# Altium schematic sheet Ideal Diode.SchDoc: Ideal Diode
size A4; Date: Not shown in title block; ApprovedBy: Hely Zhang; CheckedBy: Not shown in title block; Author: Not shown in title block; CompanyName: Not shown in title block; DrawnBy: Hely Zhang; Engineer: Not shown in title block; Organization: Not shown in title block; Address1: Not shown in title block; Address2: Not shown in title block; Address3: Not shown in title block; Address4: Not shown in title block; DocumentNumber: 1; Revision: Use project parameter SCH_Rev; SheetNumber: 15; SheetTotal: 15; PageSetup: Record=PageOptions¦CenterHorizontal=True¦CenterVertical=True¦PrintScale=0.93¦XCorrection=1.00¦YCorrection=1.00¦PrintKind=0¦BorderSize=5000000¦LeftOffset=0¦BottomOffset=0¦Orientation=2¦PaperLength=1000¦PaperWidth=1000¦Scale=100¦PaperSource=15¦PrintQuality=600¦MediaType=1¦DitherType=10¦PaperKind=Letter¦PrintScaleMode=1
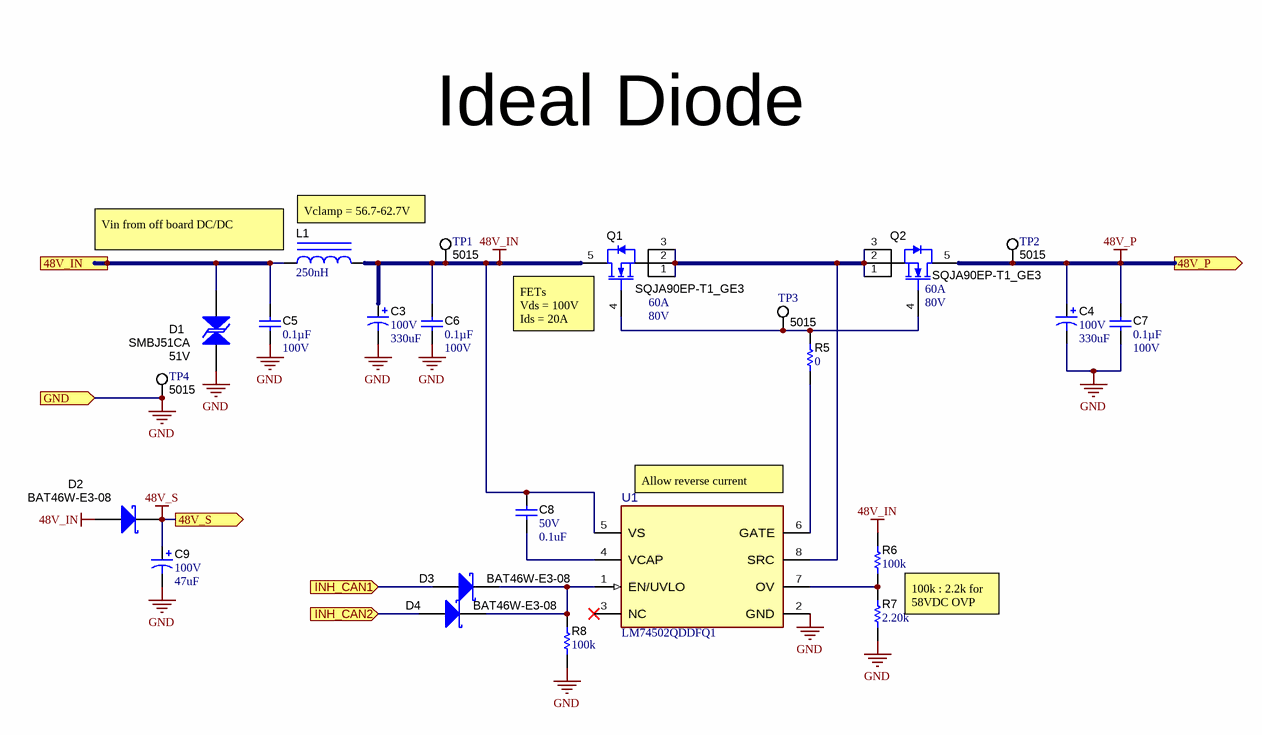
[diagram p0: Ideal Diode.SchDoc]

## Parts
C3  VDC_V: 100V  ValueDisplayed: 330uF  [CAPSMT_62_MN0]  (hidden comment: EMVE101GTR331MMN0S)
C4  VDC_V: 100V  ValueDisplayed: 330uF  [CAPSMT_62_MN0]  (hidden comment: EMVE101GTR331MMN0S)
C5  ValueDisplayed: 0.1µF  VDC_V: 100V  [0603]  (hidden comment: GCJ188L8EL104KA07D)
C6  ValueDisplayed: 0.1µF  VDC_V: 100V  [0603]  (hidden comment: GCJ188L8EL104KA07D)
C7  ValueDisplayed: 0.1µF  VDC_V: 100V  [0603]  (hidden comment: GCJ188L8EL104KA07D)
C8  VDC_V: 50V  ValueDisplayed: 0.1uF  [0402]  (hidden comment: GCM155R71H104KE02D)
C9  VDC_V: 100V  ValueDisplayed: 47uF  [SM_RADIAL_H13]  (hidden comment: EEV-FK2A470Q)
D1  SMBJ51CA  value 51V  [SMB-Bi]
D2  BAT46W-E3-08  [SOD-123]
D3  BAT46W-E3-08  [SOD-123]
D4  BAT46W-E3-08  [SOD-123]
L1  ValueDisplayed: 250nH  [WE-HCM_1390]  (hidden comment: 744309025)
Q1  SQJA90EP-T1_GE3  value 80V  IdsMax_A: 60A  [PowerPAK_SO-8L]
Q2  SQJA90EP-T1_GE3  value 80V  IdsMax_A: 60A  [PowerPAK_SO-8L]
R5  ValueDisplayed: 0  [0402]  (hidden comment: CRCW04020000Z0ED)
R6  ValueDisplayed: 100k  [0402]  (hidden comment: CRCW0402100KFKED)
R7  ValueDisplayed: 2.20k  [0402]  (hidden comment: RC0402FR-072K2L)
R8  ValueDisplayed: 100k  [0402]  (hidden comment: CRCW0402100KFKED)
TP1  5015  [Testpoint_Keystone_Miniature]
TP2  5015  [Testpoint_Keystone_Miniature]
TP3  5015  [Testpoint_Keystone_Miniature]
TP4  5015  [Testpoint_Keystone_Miniature]
U1  LM74502QDDFQ1  [DDF0008A-MFG]

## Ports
48V_IN (in), 48V_P (out), 48V_S (out), GND (in), INH_CAN1 (in), INH_CAN2 (in)

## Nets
48V_IN: C3.1(+) C6.2 C8.2 D2.2(A) L1.2 Q1.5(D) R6.2 TP1.1 U1.5(VS)
48V_P: C4.1(+) C7.2 Q2.5(D) TP2.1 ; port 48V_P
48V_S: C9.1(+) D2.1(K) ; port 48V_S
GND: C3.2(-) C4.2(-) C5.1 C6.1 C7.1 C9.2(-) D1.1 R7.1 R8.1 TP4.1 U1.2(GND) ; port GND
48V_IN: C5.2 D1.2 L1.1 ; port 48V_IN  [a separate net that carries the same name]
INH_CAN1: D3.2(A) ; port INH_CAN1
INH_CAN2: D4.2(A) ; port INH_CAN2
NetC8_1: C8.1 U1.4(VCAP)
NetD3_1: D3.1(K) D4.1(K) R8.2 U1.1(EN/UVLO)
NetQ1_1: Q1.1(S) Q1.2(S) Q1.3(S) Q2.1(S) Q2.2(S) Q2.3(S) U1.8(SRC)
NetQ1_4: Q1.4(G) Q2.4(G) R5.2 TP3.1
NetR5_1: R5.1 U1.6(GATE)
NetR6_1: R6.1 R7.2 U1.7(OV)

Not connected (* = marked no-connect by the designer): U1 3(NC)*

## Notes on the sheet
- Ideal Diode
- (near L1) Vin from off board DC/DC
- Vclamp = 56.7-62.7V
- (near Q1) FETs
  Vds = 100V
  Ids = 20A
- (near U1) Allow reverse current
- 100k : 2.2k for 58VDC OVP

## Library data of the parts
C3 C4 = CMP-0011277-1: CAP, AL, 330 uF, 100 V, +/- 20%, SMD; Manufacturer: Chemi-Con; TaMin_C: -40°C; Polarized: Y; SizeAreaWB_mm2: 441; Value1: Unknown; U/M: EA; Value: 330uF; TaMax_C: 105°C; SizeZ_mm: 21.5; SizeX_mm: 19; Cap_Case: MN0; SizeArea_mm2: 361; CompType: Capacitor; Cap_F: 330µF; IRMS_A: 980mA; AEC Category: Q200
C5-C7 = CMP-0860999-1: CAP, CERM, 0.1 µF, 100 V,+/- 10%, X8L, AEC-Q200 Grade 0, 0603; Manufacturer: MuRata; Cap_F: 100nF; TaMax_C: 150°C; SizeAreaWB_mm2: 4.68; SizeArea_mm2: 1.28; Value: 0.1uF; SizeZ_mm: 1; AEC Qualified: Y; SizeX_mm: 1.6; AEC Grade: 0; SizeY_mm: 0.8; U/M: EA; TaMin_C: -55°C; Polarized: N; AEC Category: Q200
C8 = CMP-0006356-2: CAP, CERM, 0.1 uF, 50 V, +/- 10%, X7R, AEC-Q200 Grade 1, 0402; Manufacturer: MuRata; TaMin_C: -55°C; Polarized: N; SizeAreaWB_mm2: 3; Value1: Unknown; U/M: EA; Value: 0.1uF; TaMax_C: 125°C; SizeZ_mm: 0.6; SizeX_mm: 1; SizeY_mm: 0.5; AEC Qualified: Y; Cap_F: 100nF; AEC Category: Q200
C9 = CMP-0011225-2: CAP, AL, 47 uF, 100 V, +/- 20%, 0.32 ohm, AEC-Q200 Grade 2, SMD; Manufacturer: Panasonic; TaMin_C: -55°C; ESR_ohm: 0.32; Polarized: Y; SizeAreaWB_mm2: 263.5; U/M: EA; Value: 47uF; TaMax_C: 105°C; SizeZ_mm: 13.5; SizeX_mm: 15; Cap_Case: H13; SizeArea_mm2: 202.5; CompType: Capacitor; Cap_F: 47µF; IRMS_A: 500mA; AEC Grade: 2; AEC Category: Q200
D1 = CMP-0006055-3: Diode, TVS, Bi, 51 V, 82.4 Vc, SMB; Manufacturer: Bourns; AEC Category: Q101; AEC Qualified: N; Vbr_Max: 62.7V; Value1: 600W; Vbr_Min: 56.7V; Vc: 82.4V; Ipp: 7.3A
D2-D4 = CMP-0080760-2: Diode, Schottky, 100 V, 0.15 A, AEC-Q101, SOD-123; Manufacturer: Vishay-Semiconductor; SizeArea_mm2: 6.545; Io_A: 150mA; Vr_V: 100V; Value: 100V; SizeAreaWB_mm2: 13.095; AEC Qualified: Y; Vf_V: 1V; SizeZ_mm: 1.35; Value1: 0.15A; TJmax_C: 125°C; SizeY_mm: 1.7; SizeX_mm: 3.85; AEC Category: Q101
L1 = CMP-0063911-1: Inductor, Shielded Drum Core, Ferrite, 250 nH, 50 A, 0.000165 ohm, SMD; Manufacturer: Wurth Elektronik; Isat: 81A @ 20% inductance drop; Irms: 50A @ 50C rise; Green_Lifecycle: Active; SizeAreaWB_mm2: 240; DCR_ohm: 165µ; Green_REACh: Passed; Value: 250nH; Imax_A: 50A; SizeZ_mm: 9.5; SizeX_mm: 14; SizeY_mm: 13; SizeArea_mm2: 182; AEC Category: Q200
Q1 Q2 = CMP-0086155-1: MOSFET, N-CH, 80 V, 60 A, AEC-Q101, PowerPAK_SO-8L; Alternate Manufacturer: None; Manufacturer: Vishay-Siliconix; SizeZ_mm: 1.14; SizeArea_mm2: 31.5495; ChMode: Enhancement; AEC Category: Q101; AEC Qualified: Y; Vgs_V: 20V; SizeAreaWB_mm2: 58.1095; Value2: 36 nC; Value1: ? ohm; QgTyp_nC: 36; SizeY_mm: 5.13; SizeX_mm: 6.15; ChType: N
R5 = CMP-0026822-3: RES, 0, 5%, 0.063 W, AEC-Q200 Grade 0, 0402; Manufacturer: Vishay-Dale; Power_W: 63mW; TempCo: 200 ppm/C; Value_Code: 0000; Value: 0; EIA_Code: E24; SizeX_mm: 1; SizeY_mm: 0.5; SizeZ_mm: 0.6; Value2: 0.063W; AEC Qualified: Y; VDC_V: 50V; AEC Category: Q200
R6 R8 = CMP-0025950-3: RES, 100 k, 1%, 0.063 W, AEC-Q200 Grade 0, 0402; Manufacturer: Vishay-Dale; Power_W: 63mW; TempCo: 100 ppm/C; Value: 100k; EIA_Code: E96; SizeX_mm: 1; SizeY_mm: 0.5; SizeZ_mm: 0.6; Value2: 0.063W; AEC Qualified: Y; VDC_V: 50V; AEC Category: Q200; AEC Grade: 0
R7 = CMP-0026729-1: RES, 2.20 k, 1%, 0.063 W, 0402; Manufacturer: Yageo America; Power_W: 63mW; TempCo: 100 ppm/C; Value_Code: 2k20; U/M: EA; Value: 2.20k; Res_ohm: 2.2k; SizeX_mm: 1; SizeY_mm: 0.5; SizeZ_mm: 0.6; Value2: 0.063W; AEC Qualified: N; AEC Category: Q200
TP1-TP4 = CMP-0055152-1: Test Point, Miniature, SMT; Manufacturer: Keystone; CNHeader: FALSE; Green_Lifecycle: Active; Green_REACh: Passed; CT: TRUE
U1 = CMP-0092660-1: Reverse Polarity Protection Controller with Over Voltage Protection; Manufacturer: Texas Instruments; AEC Qualified: Yes; AEC Grade: Grade 1; Max Supply Voltage: 60V; Min Supply Voltage: 4V; Nominal Supply Current: 60uA; Number Of Outputs: 1; TaMax_C: +125°C; TaMin_C: -40°C; Standoff Height: 0mm; SizeZ_mm: 1.1mm; TJmax_C: +150°C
